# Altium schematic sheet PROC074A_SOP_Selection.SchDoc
size 431 x 279 mm; Date: Not shown in title block; ApprovedBy: Not shown in title block; CheckedBy: Not shown in title block; Author: Not shown in title block; CompanyName: Not shown in title block; Engineer: Not shown in title block; Organization: Not shown in title block; Address1: Not shown in title block; Address2: Not shown in title block; Address3: Not shown in title block; Address4: Not shown in title block; DocumentNumber: 1; Revision: Use project parameter SCH_Rev; SheetNumber: 14; SheetTotal: 22; PageSetup: Record=PageOptions¦CenterHorizontal=True¦CenterVertical=True¦PrintScale=1.00¦XCorrection=1.00¦YCorrection=1.00¦PrintKind=0¦BorderSize=5000000¦LeftOffset=0¦BottomOffset=0¦Orientation=2¦PaperLength=1000¦PaperWidth=1000¦Scale=100¦PaperSource=15¦PrintQuality=600¦MediaType=1¦DitherType=10¦PaperKind=Letter¦PrintScaleMode=1
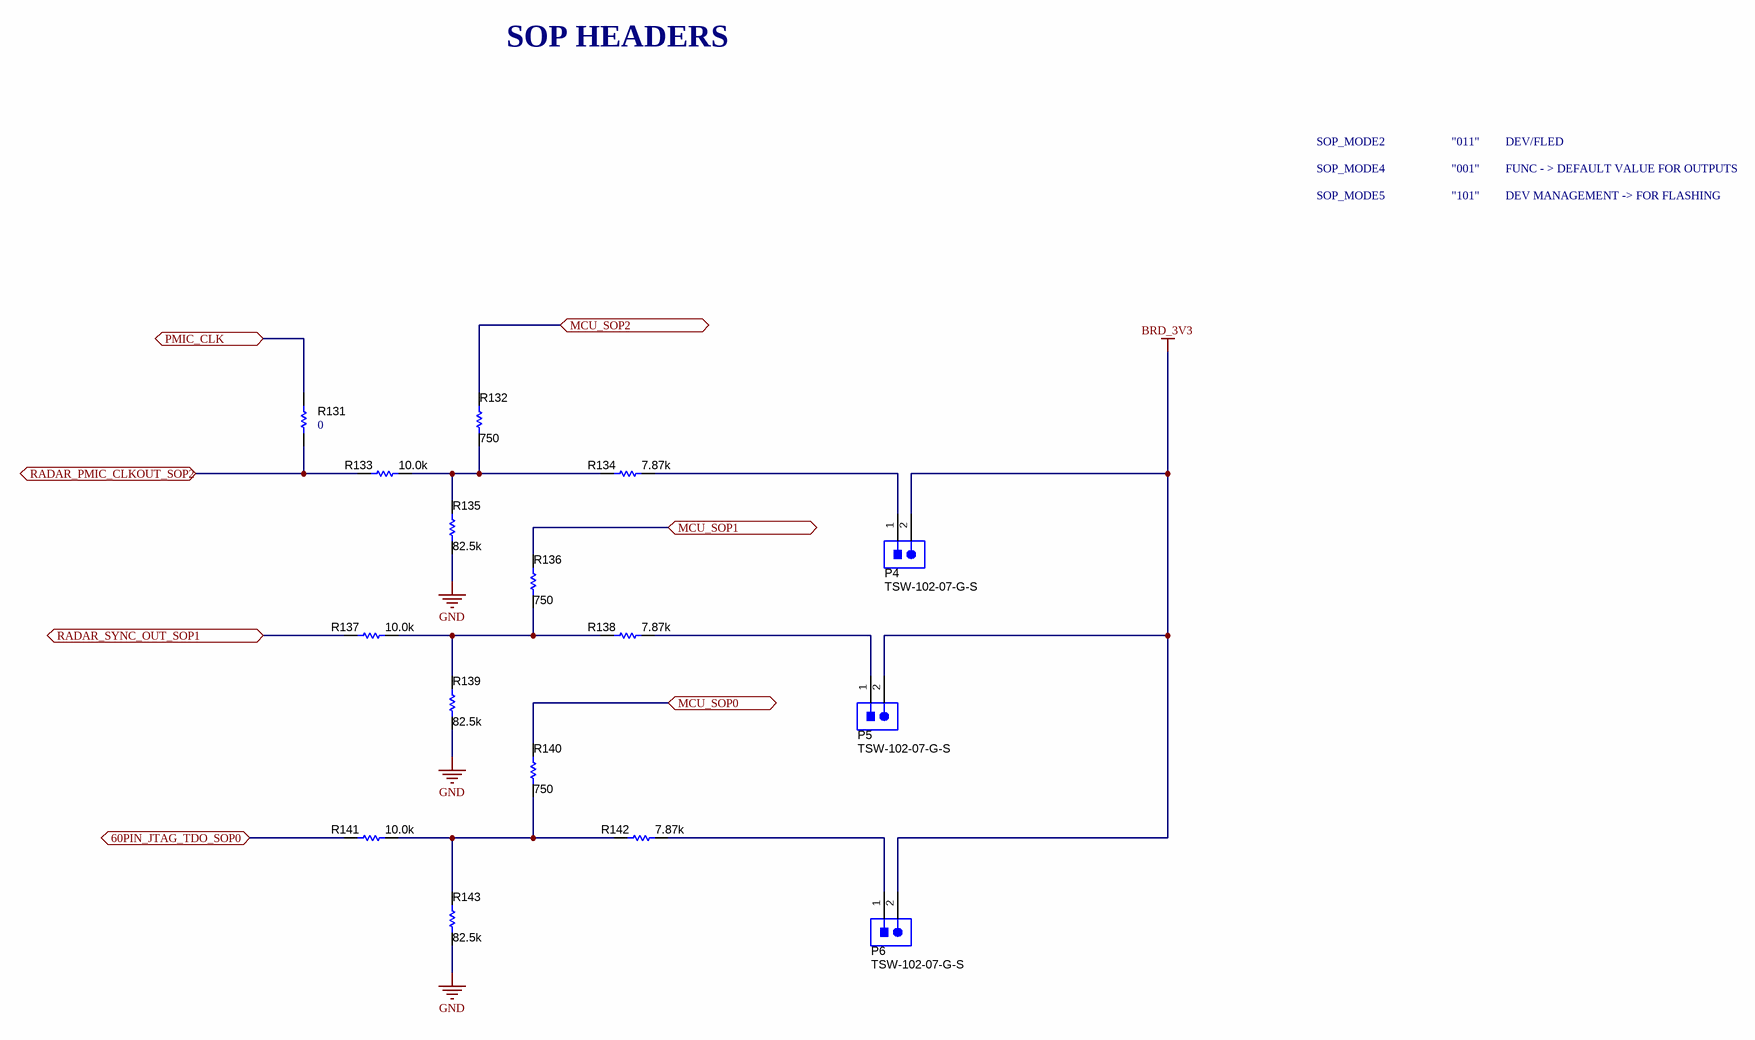
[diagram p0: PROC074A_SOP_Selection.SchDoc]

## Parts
P4  TSW-102-07-G-S  [TSW-102-07-X-S]
P5  TSW-102-07-G-S  [TSW-102-07-X-S]
P6  TSW-102-07-G-S  [TSW-102-07-X-S]
R131  ValueDisplayed: 0  [0402]  (hidden comment: ERJ-2GE0R00X)
R132  ValueDisplayed: 750  [0402L]  (hidden comment: CRCW0402750RFKED)
R133  ValueDisplayed: 10.0k  [0402L]  (hidden comment: CRCW040210K0FKED)
R134  ValueDisplayed: 7.87k  [0402L]  (hidden comment: CRCW04027K87FKED)
R135  ValueDisplayed: 82.5k  [0402L]  (hidden comment: CRCW040282K5FKED)
R136  ValueDisplayed: 750  [0402L]  (hidden comment: CRCW0402750RFKED)
R137  ValueDisplayed: 10.0k  [0402L]  (hidden comment: CRCW040210K0FKED)
R138  ValueDisplayed: 7.87k  [0402L]  (hidden comment: CRCW04027K87FKED)
R139  ValueDisplayed: 82.5k  [0402L]  (hidden comment: CRCW040282K5FKED)
R140  ValueDisplayed: 750  [0402L]  (hidden comment: CRCW0402750RFKED)
R141  ValueDisplayed: 10.0k  [0402L]  (hidden comment: CRCW040210K0FKED)
R142  ValueDisplayed: 7.87k  [0402L]  (hidden comment: CRCW04027K87FKED)
R143  ValueDisplayed: 82.5k  [0402L]  (hidden comment: CRCW040282K5FKED)

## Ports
60PIN_JTAG_TDO_SOP0, MCU_SOP0, MCU_SOP1, MCU_SOP2, PMIC_CLK, RADAR_PMIC_CLKOUT_SOP2, RADAR_SYNC_OUT_SOP1

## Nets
BRD_3V3: P4.2 P5.2 P6.2
GND: R135.1 R139.1 R143.1
60PIN_JTAG_TDO_SOP0: R141.1 ; port 60PIN_JTAG_TDO_SOP0
MCU_SOP0: R140.2 ; port MCU_SOP0
MCU_SOP1: R136.2 ; port MCU_SOP1
MCU_SOP2: R132.2 ; port MCU_SOP2
PMIC_CLK: R131.2 ; port PMIC_CLK
RADAR_PMIC_CLKOUT_SOP2: R131.1 R133.1 ; port RADAR_PMIC_CLKOUT_SOP2
RADAR_SYNC_OUT_SOP1: R137.1 ; port RADAR_SYNC_OUT_SOP1
NetP4_1: P4.1 R134.2
NetP5_1: P5.1 R138.2
NetP6_1: P6.1 R142.2
NetR132_1: R132.1 R133.2 R134.1 R135.2
NetR136_1: R136.1 R137.2 R138.1 R139.2
NetR140_1: R140.1 R141.2 R142.1 R143.2

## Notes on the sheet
- SOP HEADERS
- SOP_MODE2
- SOP_MODE4
- SOP_MODE5
- "011"
- "001"
- "101"
- DEV/FLED
- FUNC - > DEFAULT VALUE FOR OUTPUTS
- DEV MANAGEMENT -> FOR FLASHING

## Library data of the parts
P4-P6 = CMP-0075405-1: Header, 100mil, 2x1, Gold, TH; Manufacturer: Samtec; Pitch_mm: 2.54; Cert_VDE: N; Gender: Male; Cert_CSA: Y; Voltage_V: 550V; Green_REACh: Passed; Current_A: 6.3A; CT: False; Green_Lifecycle: Active; Row_Count: 1; CNHeader: True
R131 = CMP-0026992-3: RES, 0, 5%, 0.1 W, AEC-Q200 Grade 0, 0402; Manufacturer: Panasonic; Power_W: 100mW; TempCo: 600 ppm/C; Value_Code: 0000; Value: 0; EIA_Code: E24; SizeX_mm: 1; SizeY_mm: 0.5; SizeZ_mm: 0.6; Value2: 0.1W; CompType: Resistor; AEC Qualified: Y; VDC_V: 50V; AEC Category: Q200; SizeAreaWB_mm2: 3; INSTALLATION: DNP
R132 R136 R140 = CMP-0026542-1: RES, 750, 1%, 0.063 W, AEC-Q200 Grade 0, 0402; Manufacturer: Vishay-Dale; Power_W: 63mW; TempCo: 100 ppm/C; Value_Code: 750R; U/M: EA; Value: 750; EIA_Code: E96; SizeX_mm: 1; SizeY_mm: 0.5; SizeZ_mm: 0.6; Value2: 0.063W; AEC Qualified: Y; VDC_V: 50V; AEC Grade: 0; AEC Category: Q200
R133 R137 R141 = CMP-0025958-2: RES, 10.0 k, 1%, 0.063 W, 0402; Manufacturer: Vishay-Dale; Power_W: 63mW; TempCo: 100 ppm/C; Value_Code: 10k0; U/M: EA; Value: 10.0k; EIA_Code: E96; Res_ohm: 10k; SizeX_mm: 1; SizeY_mm: 0.5; SizeZ_mm: 0.6; Value2: 0.063W; VDC_V: 50V; AEC Category: Q200
R134 R138 = CMP-0026557-1: RES, 7.87 k, 1%, 0.063 W, AEC-Q200 Grade 0, 0402; Manufacturer: Vishay-Dale; Power_W: 63mW; TempCo: 100 ppm/C; Value_Code: 7k87; U/M: EA; Value: 7.87k; EIA_Code: E96; SizeX_mm: 1; SizeY_mm: 0.5; SizeZ_mm: 0.6; Value2: 0.063W; AEC Qualified: Y; VDC_V: 50V; AEC Grade: 0; AEC Category: Q200
R135 R139 R143 = CMP-0026574-1: RES, 82.5 k, 1%, 0.063 W, AEC-Q200 Grade 0, 0402; Manufacturer: Vishay-Dale; Power_W: 63mW; TempCo: 100 ppm/C; Value_Code: 82k5; U/M: EA; Value: 82.5k; EIA_Code: E96; SizeX_mm: 1; SizeY_mm: 0.5; SizeZ_mm: 0.6; Value2: 0.063W; CompType: Resistor; AEC Qualified: Y; VDC_V: 50V; AEC Grade: 0; AEC Category: Q200
R142 = CMP-0026557-1: RES, 7.87 k, 1%, 0.063 W, AEC-Q200 Grade 0, 0402; Manufacturer: Vishay-Dale; Power_W: 63mW; TempCo: 100 ppm/C; Value_Code: 7k87; U/M: EA; Value: 7.87k; EIA_Code: E96; SizeX_mm: 1; SizeY_mm: 0.5; SizeZ_mm: 0.6; Value2: 0.063W; CompType: Resistor; AEC Qualified: Y; VDC_V: 50V; AEC Grade: 0; AEC Category: Q200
